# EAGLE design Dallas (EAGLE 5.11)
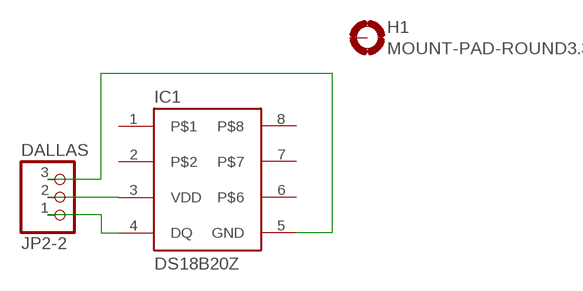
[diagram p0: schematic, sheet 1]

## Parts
H1  MOUNT-PAD-ROUND3.3  [3,3-PAD]
IC1  DS18B20Z  [SO08]
JP2-2  DALLAS  PINHD-1X3  [1X03]

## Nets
GND: IC1.5(GND) JP2-2.3
N$1: IC1.4(DQ) JP2-2.1
N$2: IC1.3(VDD) JP2-2.2
Unconnected: H1.B3,3(MOUNT) IC1.1 IC1.2 IC1.6 IC1.7 IC1.8

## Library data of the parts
H1 = holes:MOUNT-PAD-ROUND: MOUNTING PAD, round
IC1 = 1wire:DS18B20Z
JP2-2 = pinhead:PINHD-1X3: PIN HEADER

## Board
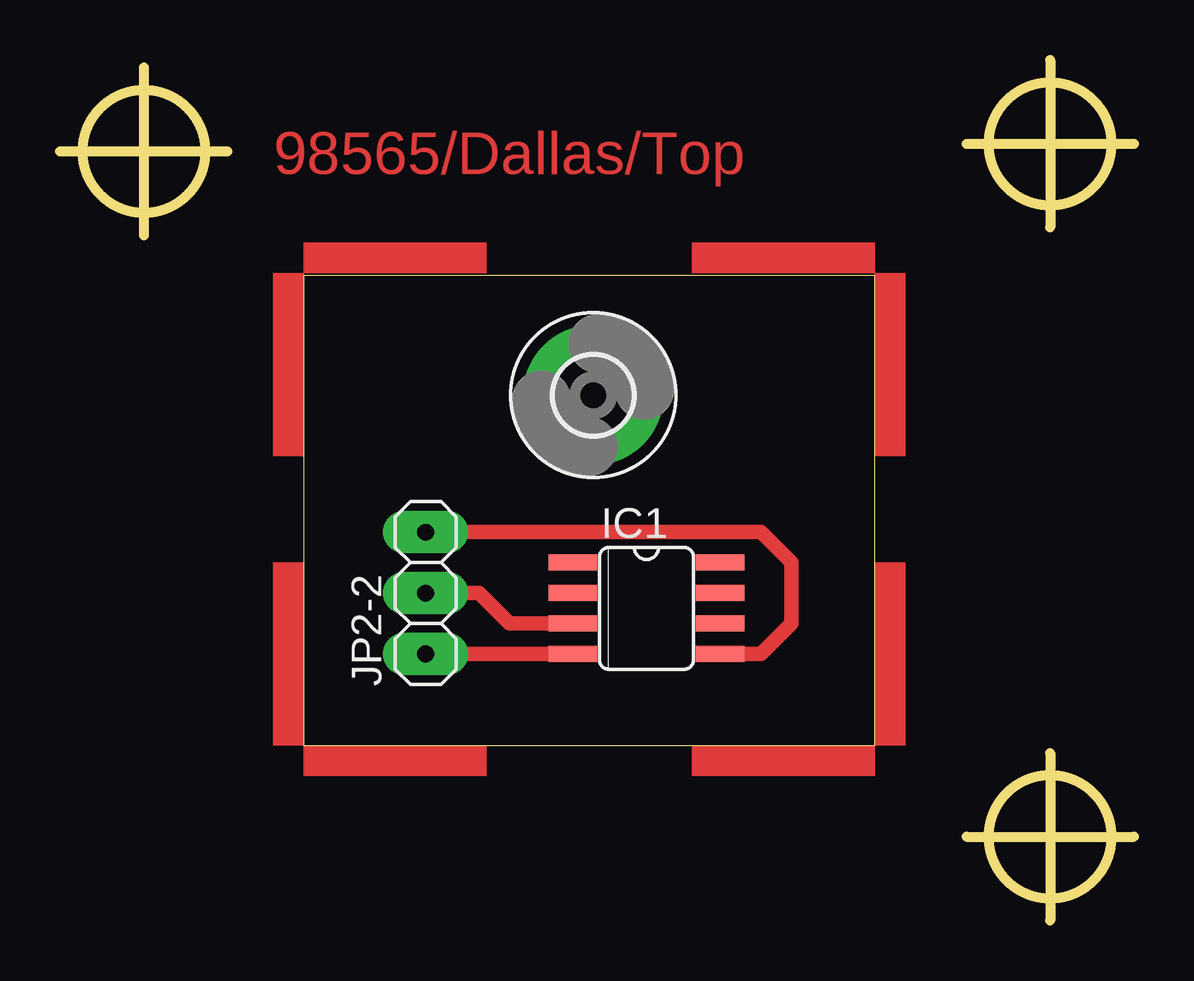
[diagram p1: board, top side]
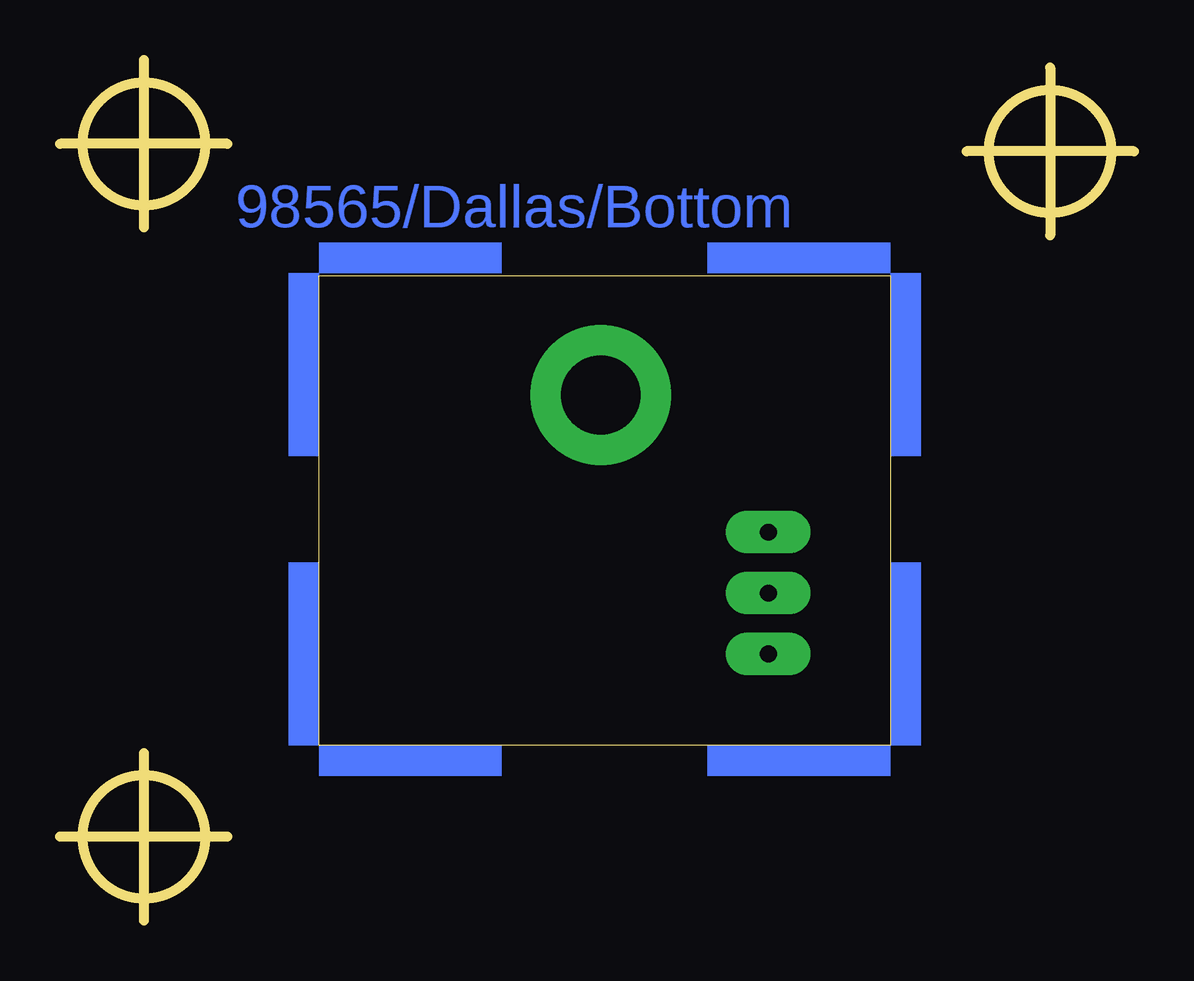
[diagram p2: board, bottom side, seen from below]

Size 44.77 x 35.88 mm. Coordinates in mm from the lower left corner, seen from the top.
Outline: 37.78,3.49 44.77,3.49
Outline: 41.27,6.98 41.27,0
Outline: 0,32.07 6.99,32.07
Outline: 3.49,35.56 3.49,28.58
Outline: 37.78,32.38 44.77,32.38
Outline: 41.27,35.88 41.27,28.89
Outline: 10.16,7.3 33.97,7.3 33.97,26.89 10.16,26.89 10.16,7.3
Outline: circle at 3.49,32.07 radius 2.56
Outline: circle at 41.27,32.38 radius 2.56
Outline: circle at 41.27,3.49 radius 2.56
Copper layers (1*16): Top 0.035mm / dielectric 1.5mm / Bottom 0.035mm
Design rules "default *": minimum track width 10mil, minimum drill 24mil, track to track 8mil, track to pad 8mil, pad to pad 8mil, via to via 8mil, smd to smd 12mil, copper to edge 40mil, drill to drill 8mil, minimum pad ring 10mil, minimum via ring 8mil, stop-mask expansion 4mil, vias tented up to drill 0mil, thermal gap 10mil

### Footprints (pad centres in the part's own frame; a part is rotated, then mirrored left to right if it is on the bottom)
3,3-PAD = drill 3.3 pad 5.842 round: B3,3 0,0
SO08 = smd 0.66 x 2.032: 1 -1.905,-3.073; 2 -0.635,-3.073; 3 0.635,-3.073; 4 1.905,-3.073; 5 1.905,3.073; 6 0.635,3.073; 7 -0.635,3.073; 8 -1.905,3.073
1X03 = drill 0.7 pad 1.778 long: 1 -2.54,0; 2 0,0; 3 2.54,0

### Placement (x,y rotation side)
H1  22.23,21.91 0 top
IC1  24.45,13.02 270 top
JP2-2  15.24,13.65 90 top
U$1  [ANGLE-ARROW-NW1-16]  10.16,26.99 0 top
U$2  [ANGLE-ARROW-NW1-16]  10.16,7.3 90 top
U$3  [ANGLE-ARROW-NW1-16]  33.97,7.3 180 top
U$4  [ANGLE-ARROW-NW1-16]  33.97,26.99 270 top

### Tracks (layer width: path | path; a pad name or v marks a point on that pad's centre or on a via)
GND
  Top 0.61: IC1.5 29.21,11.11 30.48,12.38 30.48,14.92 29.21,16.19 JP2-2.3
N$1
  Top 0.61: JP2-2.1 IC1.4
N$2
  Top 0.61: JP2-2.2 17.46,13.65 18.73,12.38 IC1.3

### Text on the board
Top: 98565/Dallas/Top
Bottom: 98565/Dallas/Bottom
